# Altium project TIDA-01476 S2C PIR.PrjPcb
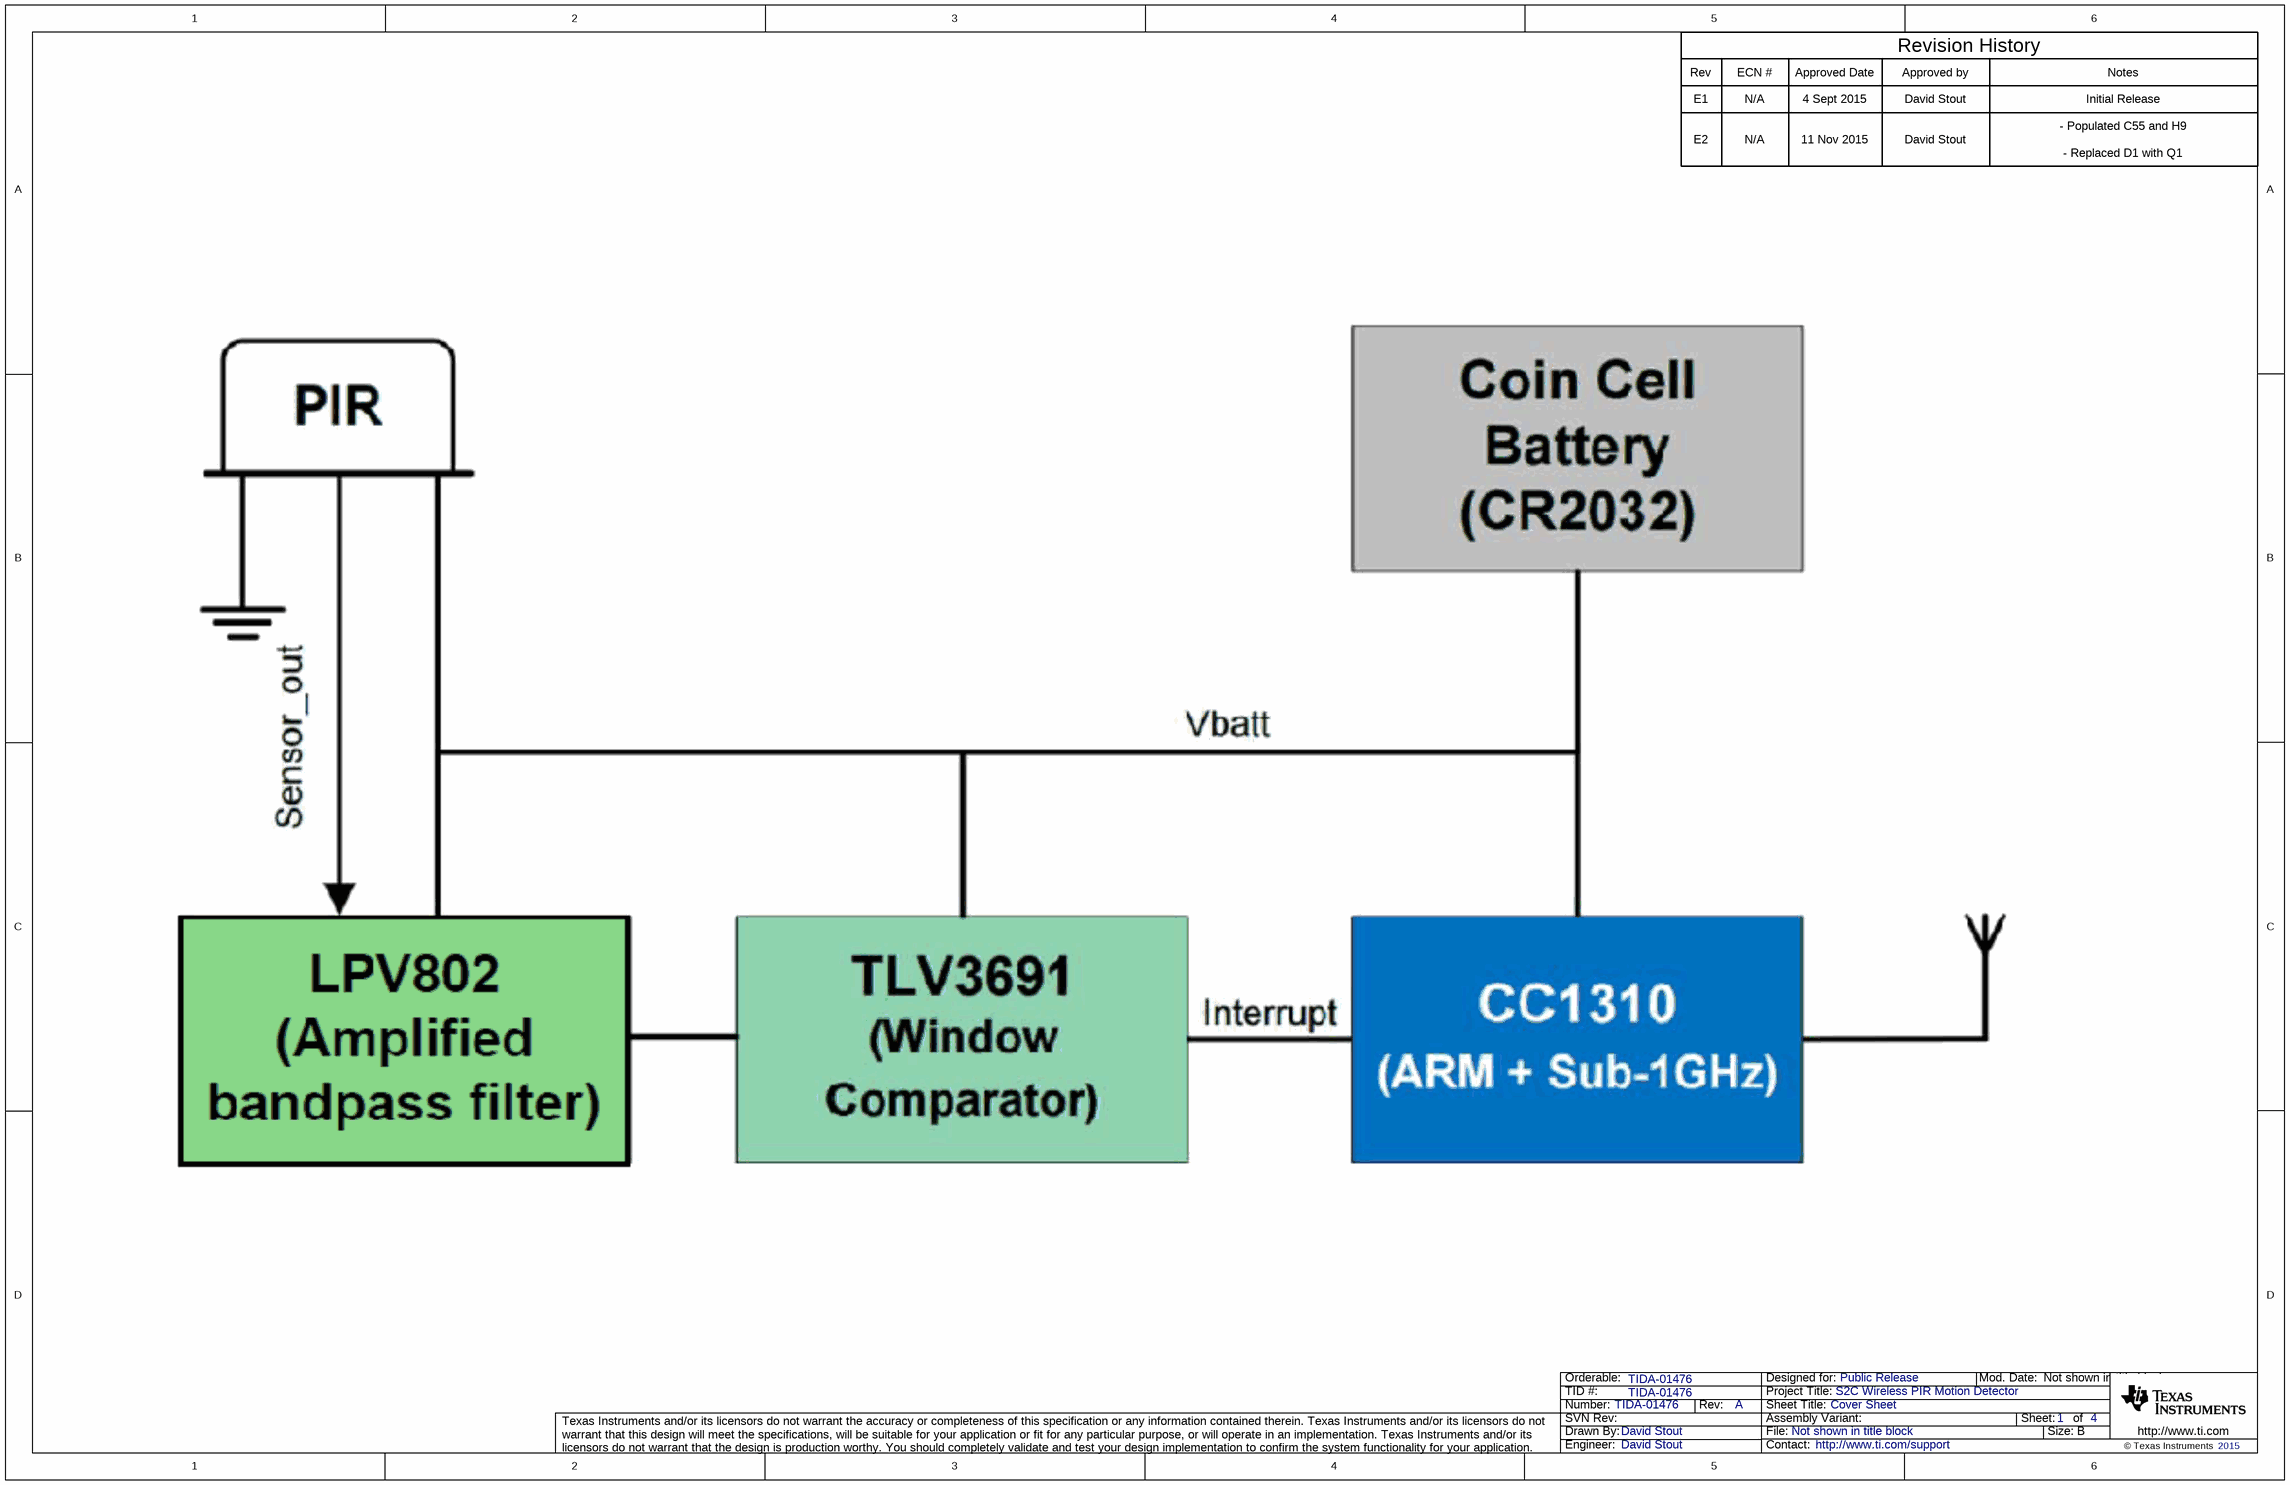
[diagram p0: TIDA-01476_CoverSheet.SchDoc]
CopyrightYear: 2015; EVM_Orderable: TIDA-01476; PCB_Layout: Krypton Solutions/RS; PCB_Rev: A; PRJ_Customer: Public Release; PRJ_Engineer: David Stout; PRJ_Number: TIDA-01476; PRJ_Title: S2C Wireless PIR Motion Detector; SCH_Rev: A; TechSupport: http://www.ti.com/support; TID: TIDA-01476
4 sheets, 141 parts. Net scope: global (net labels, ports and power ports of the same name join across sheets).
Board file: TIDA-01476.PcbDoc
Sheets:
  TIDA-01476_CoverSheet.SchDoc
  TIDA-01476_MCU.SchDoc
  TIDA-01476_POWER_PIR_802.SchDoc
  TIDA-01476_TID_Hardware.SchDoc

## Sheet TIDA-01476_CoverSheet.SchDoc: Cover Sheet
size 431 x 279 mm; Date: Not shown in title block; ApprovedBy: Not shown in title block; CheckedBy: Not shown in title block; Author: Not shown in title block; CompanyName: Not shown in title block; DrawnBy: David Stout; Engineer: Not shown in title block; Organization: Not shown in title block; Address1: Not shown in title block; Address2: Not shown in title block; Address3: Not shown in title block; Address4: Not shown in title block; DocumentNumber: 1; Revision: Use project parameter SCH_Rev; SheetNumber: 1; SheetTotal: 4; PageSetup: Record=PageOptions¦CenterHorizontal=True¦CenterVertical=True¦PrintScale=0.64¦XCorrection=1.00¦YCorrection=1.00¦PrintKind=0¦BorderSize=5000000¦LeftOffset=0¦BottomOffset=0¦Orientation=2¦PaperLength=1000¦PaperWidth=1000¦Scale=100¦PaperSource=15¦PrintQuality=1200¦MediaType=1¦DitherType=10¦PrintScaleMode=1¦PaperKind=Letter¦PaperIndex=1

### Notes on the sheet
- Rev
- E1
- ECN #
- N/A
- Approved Date
- 4 Sept 2015
- Approved by
- David Stout
- Revision History
- Notes
- Initial Release
- E2
- 11 Nov 2015
- - Populated C55 and H9
- - Replaced D1 with Q1

## Sheet TIDA-01476_MCU.SchDoc: Wireless MCU
size 431 x 279 mm; Date: Not shown in title block; ApprovedBy: Not shown in title block; CheckedBy: Not shown in title block; Author: Not shown in title block; CompanyName: Not shown in title block; DrawnBy: Evan Cornell; Engineer: Not shown in title block; Organization: Not shown in title block; Address1: Not shown in title block; Address2: Not shown in title block; Address3: Not shown in title block; Address4: Not shown in title block; DocumentNumber: 1; Revision: Use project parameter SCH_Rev; SheetNumber: 3; SheetTotal: 4; PageSetup: Record=PageOptions¦CenterHorizontal=True¦CenterVertical=True¦PrintScale=1.00¦XCorrection=1.00¦YCorrection=1.00¦PrintKind=0¦BorderSize=5000000¦LeftOffset=0¦BottomOffset=0¦Orientation=2¦PaperLength=1000¦PaperWidth=1000¦Scale=100¦PaperSource=15¦PrintQuality=600¦MediaType=1¦DitherType=10¦PaperKind=Letter¦PrintScaleMode=1
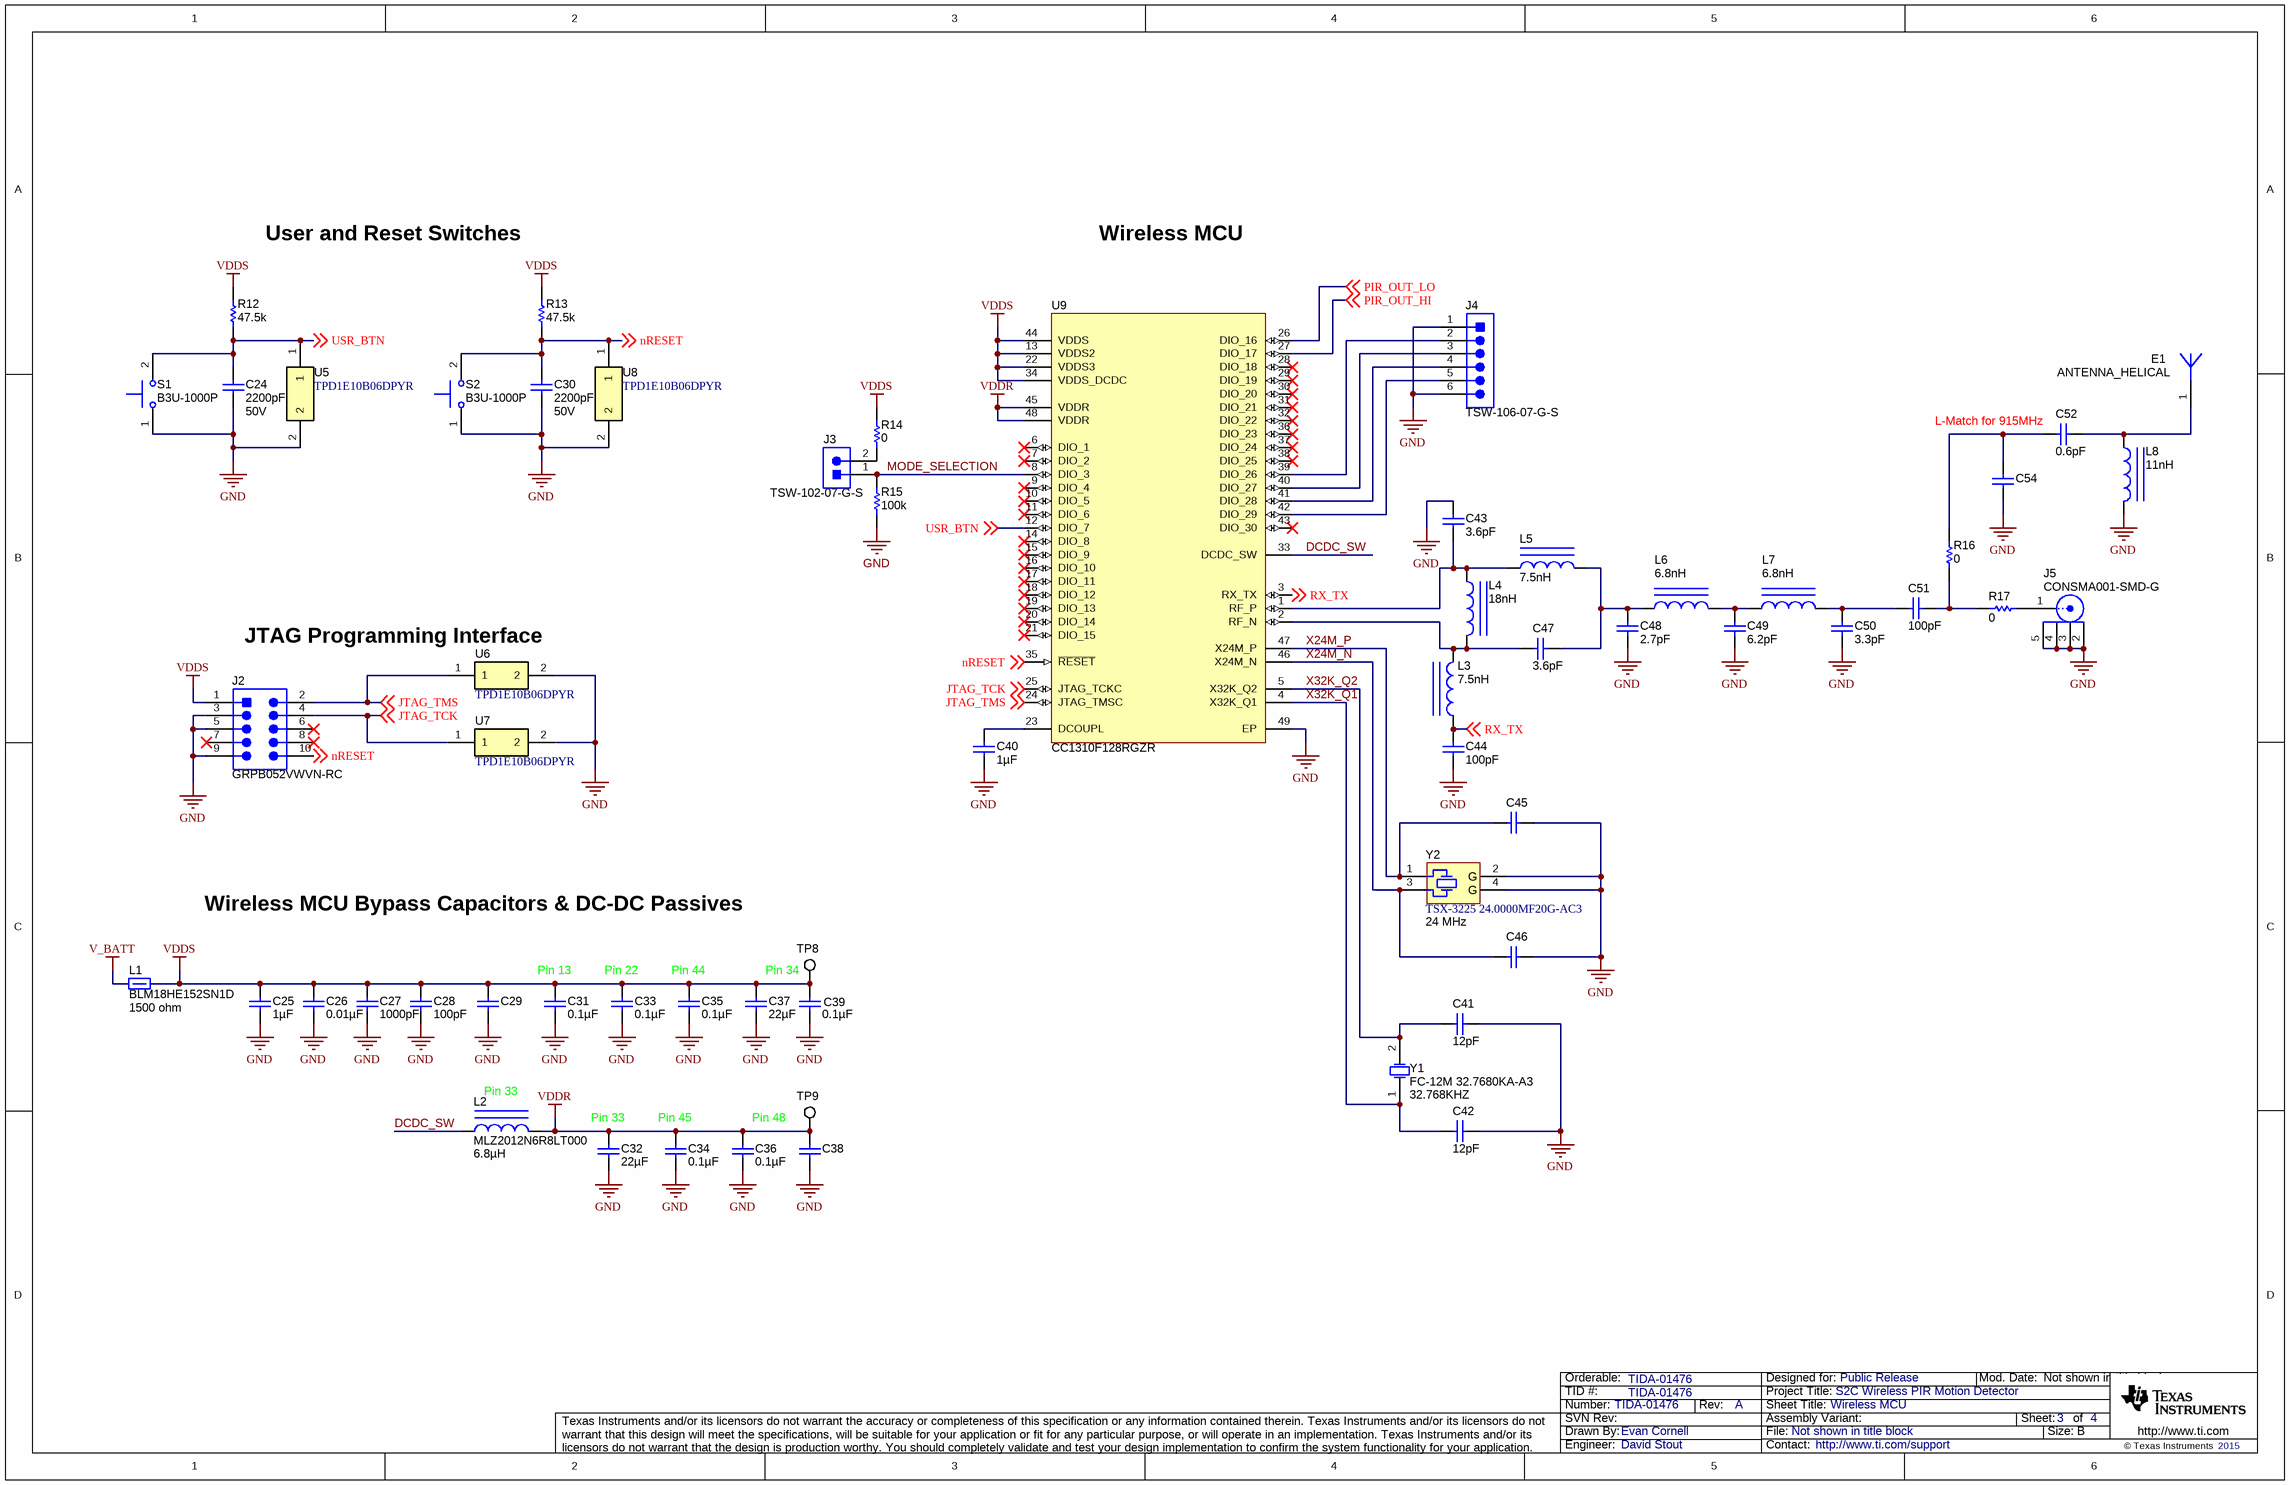
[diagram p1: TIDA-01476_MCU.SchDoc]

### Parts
C24  ValueDisplayed: 2200pF  Value2: 50V  [0402]  (hidden comment: C1005X7R1H222K)
C25  ValueDisplayed: 1µF  [0603]  (hidden comment: C1608X7R1C105K)
C26  ValueDisplayed: 0.01µF  [0402]  (hidden comment: C1005X7R1C103K)
C27  ValueDisplayed: 1000pF  [0402]  (hidden comment: C1005X7R1H102K)
C28  ValueDisplayed: 100pF  [0402]  (hidden comment: C0402C101J3GACTU)
C29  C1608X5R0J226M080AC  [0603L]  (value not drawn)
C30  ValueDisplayed: 2200pF  Value2: 50V  [0402]  (hidden comment: C1005X7R1H222K)
C31  ValueDisplayed: 0.1µF  [0402L]  (hidden comment: GRM155R70J104KA01D)
C32  ValueDisplayed: 22µF  [0603L]  (hidden comment: C1608X5R0J226M080AC)
C33  ValueDisplayed: 0.1µF  [0402L]  (hidden comment: GRM155R70J104KA01D)
C34  ValueDisplayed: 0.1µF  [0402L]  (hidden comment: GRM155R70J104KA01D)
C35  ValueDisplayed: 0.1µF  [0402L]  (hidden comment: GRM155R70J104KA01D)
C36  ValueDisplayed: 0.1µF  [0402L]  (hidden comment: GRM155R70J104KA01D)
C37  ValueDisplayed: 22µF  [0603L]  (hidden comment: C1608X5R0J226M080AC)
C38  GRM155R70J104KA01D  [0402L]  (value not drawn)
C39  ValueDisplayed: 0.1µF  [0402L]  (hidden comment: GRM155R70J104KA01D)
C40  ValueDisplayed: 1µF  [0603L]  (hidden comment: GRM188R70J105KA01D)
C41  ValueDisplayed: 12pF  [0402]  (hidden comment: GRM1555C1E120JA01D)
C42  ValueDisplayed: 12pF  [0402]  (hidden comment: GRM1555C1E120JA01D)
C43  ValueDisplayed: 3.6pF  [0402L]  (hidden comment: GRM1555C1H3R6CA01D)
C44  ValueDisplayed: 100pF  [0402L]  (hidden comment: GRM1555C1H101JA01D)
C45  GRM1555C1E120JA01D  [0402]  (value not drawn)
C46  GRM1555C1E120JA01D  [0402]  (value not drawn)
C47  ValueDisplayed: 3.6pF  [0402L]  (hidden comment: GRM1555C1H3R6CA01D)
C48  ValueDisplayed: 2.7pF  [0402L]  (hidden comment: GRM1555C1H2R7CA01D)
C49  ValueDisplayed: 6.2pF  [0402L]  (hidden comment: GRM1555C1H6R2CA01D)
C50  ValueDisplayed: 3.3pF  [0402L]  (hidden comment: GRM1555C1H3R3CA01D)
C51  ValueDisplayed: 100pF  [0402L]  (hidden comment: GRM1555C1H101JA01D)
C52  value 0.6pF  [0402]  (hidden comment: GJM1555C1HR60BB01D)
C54  GRM1555C1H1R0CA01D  [0402]  (value not drawn)
E1  ANTENNA_HELICAL  [ANTENNA_HELICAL]  (net tie)
J2  GRPB052VWVN-RC  [CONN_GRPB052VWVN-RC]
J3  TSW-102-07-G-S  [TSW-102-07-G-S]
J4  TSW-106-07-G-S  [TSW-106-07-G-S]
J5  CONSMA001-SMD-G  [Linx_CONSMA001-SMD-G]
L1  BLM18HE152SN1D  value 1500 ohm  [0603_095]
L2  MLZ2012N6R8LT000  ValueDisplayed: 6.8µH  [0805_145]
L3  ValueDisplayed: 7.5nH  [LQW15A_00_10]  (hidden comment: LQW15AN7N5G00D)
L4  value 18nH  [LQW15A_00_10]  (hidden comment: LQW15AN18NJ00D)
L5  ValueDisplayed: 7.5nH  [LQW15A_00_10]  (hidden comment: LQW15AN7N5G00D)
L6  value 6.8nH  [LQW15A_00_10]  (hidden comment: LQW15AN6N8G00D)
L7  value 6.8nH  [LQW15A_00_10]  (hidden comment: LQW15AN6N8G00D)
L8  ValueDisplayed: 11nH  [0402]  (hidden comment: LQW15AN11NG00D)
R12  ValueDisplayed: 47.5k  [0402]  (hidden comment: CRCW040247K5FKED)
R13  ValueDisplayed: 47.5k  [0402]  (hidden comment: CRCW040247K5FKED)
R14  ValueDisplayed: 0  [0402]  (hidden comment: CRCW04020000Z0ED)
R15  ValueDisplayed: 100k  [0402]  (hidden comment: CRCW0402100KFKED)
R16  ValueDisplayed: 0  [0402]  (hidden comment: CRCW04020000Z0ED)
R17  ValueDisplayed: 0  [0402]  (hidden comment: CRCW04020000Z0ED)
S1  B3U-1000P  [SW_B3U-1000P]
S2  B3U-1000P  [SW_B3U-1000P]
TP8  5015  [Testpoint_Keystone_Miniature]  (value not drawn)
TP9  5015  [Testpoint_Keystone_Miniature]  (value not drawn)
U5  TPD1E10B06DPYR  [DPY0002A]
U6  TPD1E10B06DPYR  [DPY0002A]
U7  TPD1E10B06DPYR  [DPY0002A]
U8  TPD1E10B06DPYR  [DPY0002A]
U9  CC1310F128RGZR  [RGZ0048A]
Y1  FC-12M 32.7680KA-A3  Frequency: 32.768KHZ  [Epson_FC-12M]
Y2  TSX-3225 24.0000MF20G-AC3  Frequency: 24 MHz  [EPSON_TSX-3225]

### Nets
GND: C24.1 C25.2 C26.2 C27.2 C28.2 C29.2 C30.1 C31.2 C32.2 C33.2 C34.2 C35.2 C36.2 C37.2 C38.2 C39.2 C40.1 C41.1 C42.1 C43.1 C44.2 C45.2 C46.2 C48.2 C49.2 C50.2 C54.2 J2.3 J2.5 J2.9 J4.1 J4.6 J5.2 J5.3 J5.4 J5.5 L8.2 R15.1 S1.1 S2.1 U5.2 U6.2 U7.2 U8.2 U9.49(EP) Y2.2(GND) Y2.4(GND)
V_BATT: L1.2
VDDR: C32.1 C34.1 C36.1 C38.1 L2.2 TP9.1 U9.45(VDDR) U9.48(VDDR)
VDDS: C25.1 C26.1 C27.1 C28.1 C29.1 C31.1 C33.1 C35.1 C37.1 C39.1 J2.1 L1.1 R12.2 R13.2 R14.2 TP8.1 U9.13(VDDS2) U9.22(VDDS3) U9.34(VDDS_DCDC) U9.44(VDDS)
DCDC_SW: L2.1 U9.33(DCDC_SW)
JTAG_TCK: J2.4 U7.1 U9.25(JTAG_TCKC) ; off-sheet JTAG_TCK
JTAG_TMS: J2.2 U6.1 U9.24(JTAG_TMSC) ; off-sheet JTAG_TMS
MODE_SELECTION: J3.1 R15.2 U9.8(DIO_3)
nRESET: C30.2 J2.10 R13.1 S2.2 U8.1 U9.35(~{RESET}) ; off-sheet nRESET
PIR_OUT_HI: U9.27(DIO_17) ; off-sheet PIR_OUT_HI
PIR_OUT_LO: U9.26(DIO_16) ; off-sheet PIR_OUT_LO
RX_TX: C44.1 L3.1 U9.3(RX_TX) ; off-sheet RX_TX
USR_BTN: C24.2 R12.1 S1.2 U5.1 U9.12(DIO_7) ; off-sheet USR_BTN
X24M_N: C46.1 U9.46(X24M_N) Y2.3
X24M_P: C45.1 U9.47(X24M_P) Y2.1
X32K_Q1: C42.2 U9.4(X32K_Q1) Y1.1(OSC1)
X32K_Q2: C41.2 U9.5(X32K_Q2) Y1.2(OSC2)
NetC40_2: C40.2 U9.23(DCOUPL)
NetC43_2: C43.2 L4.1 L5.1 U9.1(RF_P)
NetC47_1: C47.1 C48.1 L5.2 L6.1
NetC47_2: C47.2 L3.2 L4.2 U9.2(RF_N)
NetC49_1: C49.1 L6.2 L7.1
NetC50_1: C50.1 C51.2 L7.2
NetC51_1: C51.1 R16.1 R17.1
NetC52_1: C52.1 C54.1 R16.2
NetC52_2: C52.2 E1.1 L8.1
NetJ3_2: J3.2 R14.1
NetJ4_2: J4.2 U9.39(DIO_26)
NetJ4_3: J4.3 U9.40(DIO_27)
NetJ4_4: J4.4 U9.41(DIO_28)
NetJ4_5: J4.5 U9.42(DIO_29)
NetJ5_1: J5.1 R17.2

Not connected (* = marked no-connect by the designer): J2 6* 7* 8*; U9 6(DIO_1)* 7(DIO_2)* 9(DIO_4)* 10(DIO_5)* 11(DIO_6)* 14(DIO_8)* 15(DIO_9)* 16(DIO_10)* 17(DIO_11)* 18(DIO_12)* 19(DIO_13)* 20(DIO_14)* 21(DIO_15)* 28(DIO_18)* 29(DIO_19)* 30(DIO_20)* 31(DIO_21)* 32(DIO_22)* 36(DIO_23)* 37(DIO_24)* 38(DIO_25)* 43(DIO_30)*

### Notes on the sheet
- User and Reset Switches
- Wireless MCU
- (near C52) L-Match for 915MHz
- (near U6) JTAG Programming Interface
- Wireless MCU Bypass Capacitors & DC-DC Passives
- (near C31) Pin 13
- (near C33) Pin 22
- (near C35) Pin 44
- (near TP8) Pin 34
- (near L2) Pin 33
- (near C32) Pin 33
- (near C34) Pin 45
- Pin 48

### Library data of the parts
C24 C30 = C1005X7R1H222K: CAP, CERM, 2200 pF, 50 V, +/- 10%, X7R, 0402; Manufacturer: TDK; Polarized: N; CompType: Capacitor; Value: 2200pF; U/M: EA; Cap_F: 0.0000000022; Tolerance_%: 10; ESR_ohm: 0.1433; Value1: 0.1433 ohm; VDC_V: 50; TaMin_C: -55; TaMax_C: 125; AEC Category: Q200
C25 = C1608X7R1C105K: CAP, CERM, 1 µF, 16 V, +/- 10%, X7R, 0603; Manufacturer: TDK; Polarized: N; CompType: Capacitor; Value: 1uF; U/M: EA; Cap_F: 0.000001; Tolerance_%: 10; ESR_ohm: 0.0057; Value1: 0.0057 ohm; VDC_V: 16; Value2: 16V; TaMin_C: -55; TaMax_C: 125; AEC Category: Q200
C26 = C1005X7R1C103K: CAP, CERM, 0.01 µF, 16 V, +/- 10%, X7R, 0402; Manufacturer: TDK; Polarized: N; CompType: Capacitor; Value: 0.01uF; U/M: EA; Cap_F: 0.00000001; Tolerance_%: 10; ESR_ohm: 0.0623; Value1: 0.0623 ohm; VDC_V: 16; Value2: 16V; TaMin_C: -55; TaMax_C: 125; AEC Category: Q200
C27 = C1005X7R1H102K: CAP, CERM, 1000 pF, 50 V, +/- 10%, X7R, 0402; Manufacturer: TDK; Polarized: N; CompType: Capacitor; Value: 1000pF; U/M: EA; Cap_F: 0.000000001; Tolerance_%: 10; ESR_ohm: 0.2381; Value1: 0.2381 ohm; VDC_V: 50; Value2: 50V; TaMin_C: -55; TaMax_C: 125; AEC Category: Q200
C28 = C0402C101J3GACTU: CAP, CERM, 100 pF, 25 V, +/- 5%, C0G/NP0, 0402; Manufacturer: Kemet; Polarized: N; CompType: Capacitor; Value: 100pF; U/M: EA; Cap_F: 0.0000000001; Tolerance_%: 5; Value1: Unknown; VDC_V: 25; Value2: 25V; TaMin_C: -55; TaMax_C: 125; AEC Category: Q200
C29 = C1608X5R0J226M080AC: CAP, CERM, 22 µF, 6.3 V, +/- 20%, X5R, 0603; Manufacturer: TDK; Polarized: N; CompType: Capacitor; Value: 22uF; U/M: EA; ValueDisplayed: 22µF; Cap_F: 0.000022; Tolerance_%: 20; Value1: Unknown; VDC_V: 6.3; Value2: 6.3V; TaMin_C: -55; TaMax_C: 85; Cap_Case: 0603; AEC Category: Q200
C31 C33-C36 C39 = GRM155R70J104KA01D: CAP, CERM, 0.1 µF, 6.3 V, +/- 10%, X7R, 0402; Manufacturer: MuRata; Polarized: N; CompType: Capacitor; Value: 0.1uF; U/M: EA; Cap_F: 0.0000001; Tolerance_%: 10; Value1: Unknown; VDC_V: 6.3; Value2: 6.3V; TaMin_C: -55; TaMax_C: 125; Cap_Case: 0402; AEC Category: Q200
C32 C37 = C1608X5R0J226M080AC: CAP, CERM, 22 µF, 6.3 V, +/- 20%, X5R, 0603; Manufacturer: TDK; Polarized: N; CompType: Capacitor; Value: 22uF; U/M: EA; Cap_F: 0.000022; Tolerance_%: 20; Value1: Unknown; VDC_V: 6.3; Value2: 6.3V; TaMin_C: -55; TaMax_C: 85; Cap_Case: 0603; AEC Category: Q200
C38 = GRM155R70J104KA01D: CAP, CERM, 0.1 µF, 6.3 V, +/- 10%, X7R, 0402; Manufacturer: MuRata; Polarized: N; CompType: Capacitor; Value: 0.1uF; U/M: EA; ValueDisplayed: 0.1µF; Cap_F: 0.0000001; Tolerance_%: 10; Value1: Unknown; VDC_V: 6.3; Value2: 6.3V; TaMin_C: -55; TaMax_C: 125; Cap_Case: 0402; AEC Category: Q200
C40 = GRM188R70J105KA01D: CAP, CERM, 1 µF, 6.3 V, +/- 10%, X7R, 0603; Manufacturer: MuRata; Polarized: N; CompType: Capacitor; Value: 1uF; U/M: EA; Cap_F: 0.000001; Tolerance_%: 10; Value1: Unknown; VDC_V: 6.3; Value2: 6.3V; TaMin_C: -55; TaMax_C: 125; Cap_Case: 0603; AEC Category: Q200
C41 C42 C45 C46 = GRM1555C1E120JA01D: CAP, CERM, 12 pF, 25 V, +/- 5%, C0G/NP0, 0402; Manufacturer: MuRata; Polarized: N; CompType: Capacitor; Value: 12pF; U/M: EA; Cap_F: 0.000000000012; Tolerance_%: 5; Value1: Unknown; VDC_V: 25; Value2: 25V; TaMin_C: -55; TaMax_C: 125; AEC Category: Q200
C43 C47 = GRM1555C1H3R6CA01D: CAP, CERM, 3.6 pF, 50 V, +/- 5%, C0G/NP0, 0402; Manufacturer: MuRata; Polarized: N; CompType: Capacitor; Value: 3.6pF; U/M: EA; Cap_F: 0.0000000000036; Tolerance_%: 5; Value1: Unknown; VDC_V: 50; Value2: 50V; TaMin_C: -55; TaMax_C: 125; Cap_Case: 0402; AEC Category: Q200
C44 C51 = GRM1555C1H101JA01D: CAP, CERM, 100 pF, 50 V, +/- 5%, C0G/NP0, 0402; Manufacturer: MuRata; Polarized: N; CompType: Capacitor; Value: 100pF; U/M: EA; Cap_F: 0.0000000001; Tolerance_%: 5; Value1: Unknown; VDC_V: 50; Value2: 50V; TaMin_C: -55; TaMax_C: 125; Cap_Case: 0402; AEC Category: Q200
C48 = GRM1555C1H2R7CA01D: CAP, CERM, 2.7 pF, 50 V, +/- 5%, C0G/NP0, 0402; Manufacturer: MuRata; Polarized: N; CompType: Capacitor; Value: 2.7pF; U/M: EA; Cap_F: 0.0000000000027; Tolerance_%: 5; Value1: Unknown; VDC_V: 50; Value2: 50V; TaMin_C: -55; TaMax_C: 125; Cap_Case: 0402; AEC Category: Q200
C49 = GRM1555C1H6R2CA01D: CAP, CERM, 6.2 pF, 50 V, +/- 5%, C0G/NP0, 0402; Manufacturer: MuRata; Polarized: N; CompType: Capacitor; Value: 6.2pF; U/M: EA; Cap_F: 0.0000000000062; Tolerance_%: 5; Value1: Unknown; VDC_V: 50; Value2: 50V; TaMin_C: -55; TaMax_C: 125; Cap_Case: 0402; AEC Category: Q200
C50 = GRM1555C1H3R3CA01D: CAP, CERM, 3.3 pF, 50 V, +/- 5%, C0G/NP0, 0402; Manufacturer: MuRata; Polarized: N; CompType: Capacitor; Value: 3.3pF; U/M: EA; Cap_F: 0.0000000000033; Tolerance_%: 5; Value1: Unknown; VDC_V: 50; Value2: 50V; TaMin_C: -55; TaMax_C: 125; Cap_Case: 0402; AEC Category: Q200
C52 = Capacitor: CAP, CERM, 0.6pF, 50V, NP0/C0G, +-0.1pF, 0402; Manufacturer: Murata; Polarized: N; U/M: EA
C54 = GRM1555C1H1R0CA01D: CAP, CERM, 1 pF, 50 V, +/- 5%, C0G/NP0, 0402; Manufacturer: MuRata; CompType: Capacitor; Value: 1pF; Value1: Unknown; Value2: 50V; Polarized: N; U/M: EA; Cap_F: 0.000000000001; Tolerance_%: 5; VDC_V: 50; TaMin_C: -55; TaMax_C: 125; AEC Category: Q200
E1 = ANTENNA_HELICAL: PCB Antenna. There is nothing to buy or mount.; SymbolCreator: Altium
J2 = GRPB052VWVN-RC: Header, 50mil, 5x2, Gold, TH; Manufacturer: Sullins Connector Solutions; SymbolCreator: a0412235; U/M: EA
J3 = TSW-102-07-G-S: Header, 100mil, 2x1, Gold, TH; Manufacturer: Samtec; SymbolCreator: a0412235; U/M: EA
J4 = TSW-106-07-G-S: Header, 100mil, 6x1, Gold, TH; Manufacturer: Samtec; SymbolCreator: a0412235; U/M: EA
J5 = CONSMA001-SMD-G: Jack, SMA, PCB, Gold, SMT; Manufacturer: Linx Technologies; SymbolCreator: X0208326; U/M: EA
L1 = BLM18HE152SN1D: Ferrite Bead, 1500 ohm @ 100 MHz, 0.5 A, 0603; Manufacturer: MuRata; Imax_A: 0.5; Value1: 0.5 ohm; Value2: 0.5A; ZTyp@100MHz_Ohm: 1500
L2 = MLZ2012N6R8LT000: Inductor, Multilayer, Ferrite, 6.8 µH, 0.11 A, 0.25 ohm, SMD; Manufacturer: TDK; Value: 6.8uH; Ind_H: 6.8E-6; Imax_A: 0.11; Irms: 0.55A @ 20C rise; Isat: 0.11A @ 50% inductance drop; DCR_ohm: 0.25; Value2: 0.11A; AEC Category: Q200
L3 L5 = LQW15AN7N5G00D: Inductor, Wirewound, 7.5 nH, 0.57 A, 0.13 ohm, SMD; Manufacturer: MuRata; Value: 7.5nH; Ind_H: 7.5E-9; Imax_A: 0.57; Irms: 0.57A @ C rise; DCR_ohm: 0.13; Value2: 0.57A
L4 = LQW15AN18NJ00D: Inductor, Wirewound, 18 nH, 0.37 A, 0.27 ohm, SMD; Manufacturer: MuRata; Ind_H: 18.0E-9; Imax_A: 0.37; DCR_ohm: 0.27; Value2: 0.37A
L6 L7 = LQW15AN6N8G00D: Inductor, Wirewound, 6.8 nH, 0.7 A, 0.09 ohm, SMD; Manufacturer: MuRata; Ind_H: 6.8E-9; Imax_A: 0.7; DCR_ohm: 0.09; Value2: 0.7A
L8 = LQW15AN11NG00D: Inductor, Wirewound, 11 nH, 0.5 A, 0.14 ohm, SMD; Manufacturer: MuRata; Value: 11nH; Ind_H: 11.0E-9; Imax_A: 0.5; Isat: 0.5A @ % inductance drop; DCR_ohm: 0.14; Value2: 0.5A; AEC Category: Q200; AEC Qualified: N
R12 R13 = CRCW040247K5FKED: RES, 47.5 k, 1%, 0.063 W, 0402; Manufacturer: Vishay-Dale; CompType: Resistor; Res_ohm: 47500; Value: 47.5k; Value_Code: 47k5; Tolerance_%: 1; Power_W: 0.063; Value2: 0.063W; VDC_V: 50; TempCo: 100 ppm/C; EIA_Code: E96; U/M: EA; AEC Category: Q200
R14 R16 R17 = CRCW04020000Z0ED: RES, 0, 5%, 0.063 W, 0402; Manufacturer: Vishay-Dale; CompType: Resistor; Value: 0; Value_Code: 0000; Tolerance_%: 5; Power_W: 0.063; Value2: 0.063W; VDC_V: 50; TempCo: 200 ppm/C; EIA_Code: E24; U/M: EA; AEC Category: Q200
R15 = CRCW0402100KFKED: RES, 100 k, 1%, 0.063 W, 0402; Manufacturer: Vishay-Dale; CompType: Resistor; Value: 100k; Res_ohm: 100000; Tolerance_%: 1; Power_W: 0.063; Value2: 0.063W; VDC_V: 50; TempCo: 100 ppm/C; EIA_Code: E96; U/M: EA; AEC Category: Q200
S1 S2 = B3U-1000P: SWITCH TACTILE SPST-NO 0.05A 12V; Manufacturer: Omron Electronic Components; SymbolCreator: a0412235; VDC_V: 12; SwitchFunction: Off-Mom; PositionCount: 1; CurrentRating_mA: 50
TP8 TP9 = 5015: Test Point, Miniature, SMT; Manufacturer: Keystone; CompType: Test Point Loop; U/M: EA
U5-U8 = TPD1E10B06DPYR: ESD in 0402 Package with 10 pF Capacitance and 6 V Breakdown, 1 Channel, -40 to +125 degC, 2-pin X2SON (DPY), Green (RoHS & no Sb/Br); Manufacturer: Texas Instruments; Alternate PartNumber: Equivalent; Breakdown Voltage(Min)(V): 6; Eco-Plan: TBD; IEC 61000-4-2 Air-Gap(+/- kV): 30; IO Capacitance(Typ)(pF): 10; SubFamily: ESD Solution
U9 = CC1310F128RGZR: Sub-1 GHz and 2.4 GHz Multi-standard RF IC Family, RGZ0048A; Alternate PartNumber: CC1310F128RGZT; Manufacturer: Texas Instruments; SymbolCreator: Altium; U/M: EA
Y1 = FC-12M 32.7680KA-A3: Crystal, 32.768kHz, 12.5pF, SMD; Manufacturer: Epson; SymbolCreator: a0412235; U/M: EA; TaMin_C: -40; TaMax_C: 85; Frequency Stability: ±20ppm
Y2 = TSX-3225 24.0000MF20G-AC3: Crystal, 24 MHz, 9 pF, SMD; Manufacturer: Epson; SymbolCreator: a0412235; U/M: EA; TaMin_C: -40; TaMax_C: 85; Frequency Stability: ±20ppm

## Sheet TIDA-01476_POWER_PIR_802.SchDoc: Power and PIR Sensor
size 431 x 279 mm; Date: Not shown in title block; ApprovedBy: Not shown in title block; CheckedBy: Not shown in title block; Author: Not shown in title block; CompanyName: Not shown in title block; DrawnBy: Evan Cornell; Engineer: Not shown in title block; Organization: Not shown in title block; Address1: Not shown in title block; Address2: Not shown in title block; Address3: Not shown in title block; Address4: Not shown in title block; DocumentNumber: 1; Revision: Use project parameter SCH_Rev; SheetNumber: 2; SheetTotal: 4; PageSetup: Record=PageOptions¦CenterHorizontal=True¦CenterVertical=True¦PrintScale=0.64¦XCorrection=1.00¦YCorrection=1.00¦PrintKind=0¦BorderSize=5000000¦LeftOffset=0¦BottomOffset=0¦Orientation=2¦PaperLength=1000¦PaperWidth=1000¦Scale=100¦PaperSource=15¦PrintQuality=600¦MediaType=1¦DitherType=10¦PrintScaleMode=1¦PaperKind=Letter (8.5 x 11")¦PaperIndex=1
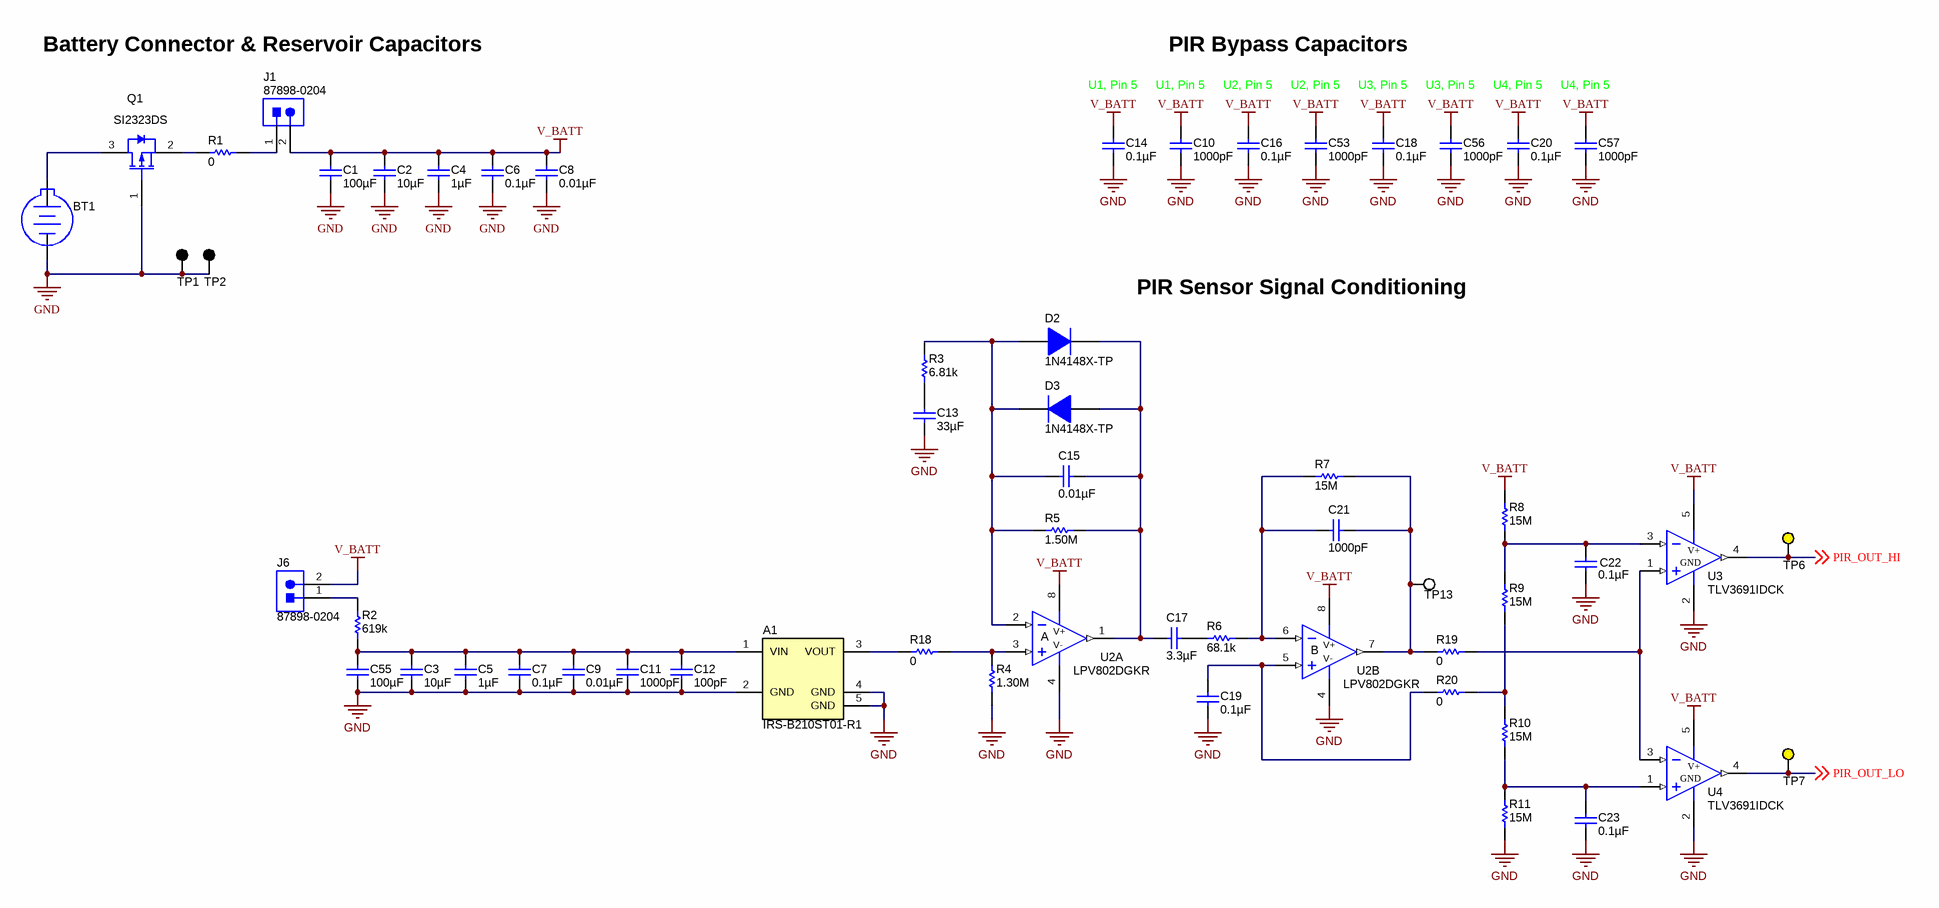
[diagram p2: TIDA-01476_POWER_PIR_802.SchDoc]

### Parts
A1  IRS-B210ST01-R1  [Murata_IRS-B210ST01]
BT1  BS-7  [BAT_BS-7]  (value not drawn)
C1  ValueDisplayed: 100µF  [1206_190]  (hidden comment: C3216X5R1A107M160AC)
C2  ValueDisplayed: 10µF  [0603]  (hidden comment: C1608X5R0J106M)
C3  ValueDisplayed: 10µF  [0402]  (hidden comment: GRM155R60J106ME44D)
C4  ValueDisplayed: 1µF  [0603]  (hidden comment: C1608X7R1C105K)
C5  ValueDisplayed: 1µF  [0402]  (hidden comment: C1005X5R1A105K050BB)
C6  ValueDisplayed: 0.1µF  [0402]  (hidden comment: C1005X7R1H104K050BB)
C7  ValueDisplayed: 0.1µF  [0402]  (hidden comment: C1005X7R1H104K050BB)
C8  ValueDisplayed: 0.01µF  [0402]  (hidden comment: C1005X7R1C103K)
C9  ValueDisplayed: 0.01µF  [0402]  (hidden comment: C1005X7R1C103K)
C10  ValueDisplayed: 1000pF  [0402]  (hidden comment: C1005X7R1H102K)
C11  ValueDisplayed: 1000pF  [0402]  (hidden comment: C1005X7R1H102K)
C12  ValueDisplayed: 100pF  [0402]  (hidden comment: C0402C101J3GACTU)
C13  ValueDisplayed: 33µF  [0805_145]  (hidden comment: C2012X5R1A336M125AC)
C14  ValueDisplayed: 0.1µF  [0402]  (hidden comment: C1005X7R1H104K)
C15  ValueDisplayed: 0.01µF  [0402]  (hidden comment: C1005X7R1E103K)
C16  ValueDisplayed: 0.1µF  [0402]  (hidden comment: C1005X7R1H104K)
C17  ValueDisplayed: 3.3µF  [0402]  (hidden comment: C1005X5R1A335K050BC)
C18  ValueDisplayed: 0.1µF  [0402]  (hidden comment: C1005X7R1H104K)
C19  ValueDisplayed: 0.1µF  [0402]  (hidden comment: C1005X7R1H104K)
C20  ValueDisplayed: 0.1µF  [0402]  (hidden comment: C1005X7R1H104K)
C21  ValueDisplayed: 1000pF  [0402]  (hidden comment: C1005C0G1E102J)
C22  ValueDisplayed: 0.1µF  [0402]  (hidden comment: C1005X7R1H104K)
C23  ValueDisplayed: 0.1µF  [0402]  (hidden comment: C1005X7R1H104K)
C53  ValueDisplayed: 1000pF  [0402]  (hidden comment: C1005X7R1H102K)
C55  ValueDisplayed: 100µF  [1206_190]  (hidden comment: C3216X5R1A107M160AC)
C56  ValueDisplayed: 1000pF  [0402]  (hidden comment: C1005X7R1H102K)
C57  ValueDisplayed: 1000pF  [0402]  (hidden comment: C1005X7R1H102K)
D2  1N4148X-TP  [SOD-523]
D3  1N4148X-TP  [SOD-523]
J1  87898-0204  [Molex_87898-0204]
J6  87898-0204  [Molex_87898-0204]
Q1  SI2323DS  [SOT-23]
R1  ValueDisplayed: 0  [0805_HV]  (hidden comment: CRCW08050000Z0EA)
R2  ValueDisplayed: 619k  [0402]  (hidden comment: CRCW0402619KFKED)
R3  ValueDisplayed: 6.81k  [0402]  (hidden comment: CRCW04026K81FKED)
R4  ValueDisplayed: 1.30M  [0402]  (hidden comment: CRCW04021M30FKED)
R5  ValueDisplayed: 1.50M  [0402]  (hidden comment: CRCW04021M50FKED)
R6  ValueDisplayed: 68.1k  [0402]  (hidden comment: CRCW040268K1FKED)
R7  ValueDisplayed: 15M  [0805_HV]  (hidden comment: RMCF0805JT15M0)
R8  ValueDisplayed: 15M  [0805_HV]  (hidden comment: RMCF0805JT15M0)
R9  ValueDisplayed: 15M  [0805_HV]  (hidden comment: RMCF0805JT15M0)
R10  ValueDisplayed: 15M  [0805_HV]  (hidden comment: RMCF0805JT15M0)
R11  ValueDisplayed: 15M  [0805_HV]  (hidden comment: RMCF0805JT15M0)
R18  ValueDisplayed: 0  [0402]  (hidden comment: CRCW04020000Z0ED)
R19  ValueDisplayed: 0  [0402]  (hidden comment: CRCW04020000Z0ED)
R20  ValueDisplayed: 0  [0402]  (hidden comment: CRCW04020000Z0ED)
TP1  5001  [Keystone5001]  (value not drawn)
TP2  5001  [Keystone5001]  (value not drawn)
TP6  5004  [Keystone5004]  (value not drawn)
TP7  5004  [Keystone5004]  (value not drawn)
TP13  5015  [Testpoint_Keystone_Miniature]  (value not drawn)
U2  LPV802DGKR  [DGK0008A_N]  (parts A,B of 2)
U3  TLV3691IDCK  [DCK0005A_N]
U4  TLV3691IDCK  [DCK0005A_N]

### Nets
GND: A1.2(GND) A1.4(GND) A1.5(GND) BT1.2(-) C1.2 C2.2 C3.2 C4.2 C5.2 C6.2 C7.2 C8.2 C9.2 C10.2 C11.2 C12.2 C13.2 C14.1 C16.1 C18.1 C19.2 C20.1 C22.2 C23.2 C53.2 C55.2 C56.2 C57.2 Q1.1(G) R4.1 R11.1 TP1.1 TP2.1 U2.4(V-) U3.2(GND) U4.2(GND)
V_BATT: C1.1 C2.1 C4.1 C6.1 C8.1 C10.1 C14.2 C16.2 C18.2 C20.2 C53.1 C56.1 C57.1 J1.2 J6.2 R8.2 U2.8(V+) U3.5(V+) U4.5(V+)
PIR_OUT_HI: TP6.1 U3.4(OUT) ; off-sheet PIR_OUT_HI
PIR_OUT_LO: TP7.1 U4.4(OUT) ; off-sheet PIR_OUT_LO
NetA1_1: A1.1(VIN) C3.1 C5.1 C7.1 C9.1 C11.1 C12.1 C55.1 R2.1
NetA1_3: A1.3(VOUT) R18.1
NetBT1_1: BT1.1(+) Q1.3(D)
NetC13_1: C13.1 R3.1
NetC15_1: C15.1 C17.2 D2.1(K) D3.2(A) R5.2 U2.1(OUT)
NetC15_2: C15.2 D2.2(A) D3.1(K) R3.2 R5.1 U2.2(IN-)
NetC17_1: C17.1 R6.1
NetC19_1: C19.1 R20.1 U2.5(IN+)
NetC21_1: C21.1 R7.2 R19.1 TP13.1 U2.7(OUT)
NetC21_2: C21.2 R6.2 R7.1 U2.6(IN-)
NetC22_1: C22.1 R8.1 R9.2 U3.3(IN-)
NetC23_1: C23.1 R10.1 R11.2 U4.1(IN+)
NetJ1_1: J1.1 R1.2
NetJ6_1: J6.1 R2.2
NetQ1_2: Q1.2(S) R1.1
NetR4_2: R4.2 R18.2 U2.3(IN+)
NetR9_1: R9.1 R10.2 R20.2
NetR19_2: R19.2 U3.1(IN+) U4.3(IN-)

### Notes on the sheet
- Battery Connector & Reservoir Capacitors
- PIR Bypass Capacitors
- U1, Pin 5
- U2, Pin 5
- U3, Pin 5
- U4, Pin 5
- PIR Sensor Signal Conditioning

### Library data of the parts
A1 = IRS-B210ST01-R1: Pyroelectric Infrared Sensors for Reflow Soldering, 3.6mVp-p, SMD; Manufacturer: MuRata; SymbolCreator: Altium; CompType: SENSOR
BT1 = BS-7: Battery Holder, CR2032, Retainer clip, TH; Manufacturer: Memory Protection Devices; SymbolCreator: a0412235
C1 C55 = C3216X5R1A107M160AC: CAP, CERM, 100 µF, 10 V, +/- 20%, X5R, 1206_190; Manufacturer: TDK; Polarized: N; CompType: Capacitor; Value: 100uF; U/M: EA; Cap_F: 0.0001; Tolerance_%: 20; Value1: Unknown; VDC_V: 10; Value2: 10V; TaMin_C: -55; TaMax_C: 85; Cap_Case: 1206; AEC Category: Q200
C2 = C1608X5R0J106M: CAP, CERM, 10 µF, 6.3 V, +/- 20%, X5R, 0603; Manufacturer: TDK; Polarized: N; CompType: Capacitor; Value: 10uF; U/M: EA; Cap_F: 0.00001; Tolerance_%: 20; ESR_ohm: 0.005; Value1: 0.005 ohm; VDC_V: 6.3; Value2: 6.3V; IRMS_A: 1.9; TaMin_C: -25; TaMax_C: 85; AEC Category: Q200
C3 = GRM155R60J106ME44D: CAP, CERM, 10 µF, 6.3 V, +/- 20%, X5R, 0402; Manufacturer: MuRata; Polarized: N; CompType: Capacitor; Value: 10uF; U/M: EA; Cap_F: 0.00001; Tolerance_%: 20; Value1: Unknown; VDC_V: 6.3; Value2: 6.3V; TaMin_C: -55; TaMax_C: 85; AEC Category: Q200
C4 = C1608X7R1C105K: as C25 on sheet TIDA-01476_MCU
C5 = C1005X5R1A105K050BB: CAP, CERM, 1 µF, 10 V, +/- 10%, X5R, 0402; Manufacturer: TDK; Polarized: N; CompType: Capacitor; Value: 1uF; U/M: EA; Cap_F: 0.000001; Tolerance_%: 10; Value1: Unknown; Value2: 10V; TaMin_C: -55; TaMax_C: 85; AEC Category: Q200
C6 C7 = C1005X7R1H104K050BB: CAP, CERM, 0.1 µF, 50 V, +/- 10%, X7R, 0402; Manufacturer: TDK; Polarized: N; CompType: Capacitor; Value: 0.1uF; U/M: EA; Cap_F: 0.0000001; Tolerance_%: 10; Value1: Unknown; VDC_V: 50; Value2: 50V; TaMin_C: -55; TaMax_C: 125; AEC Category: Q200
C8 C9 = C1005X7R1C103K: as C26 on sheet TIDA-01476_MCU
C10 C11 C53 C56 C57 = C1005X7R1H102K: as C27 on sheet TIDA-01476_MCU
C12 = C0402C101J3GACTU: as C28 on sheet TIDA-01476_MCU
C13 = C2012X5R1A336M125AC: CAP, CERM, 33 µF, 10 V, +/- 20%, X5R, 0805; Manufacturer: TDK; Polarized: N; CompType: Capacitor; Value: 33uF; U/M: EA; Cap_F: 0.000033; Tolerance_%: 20; Value1: Unknown; VDC_V: 10; Value2: 10V; TaMin_C: -55; TaMax_C: 85; Cap_Case: 0805; AEC Category: Q200
C14 C16 C18-C20 C22 C23 = C1005X7R1H104K: CAP, CERM, 0.1 µF, 50 V, +/- 10%, X7R, 0402; Manufacturer: TDK; Polarized: N; CompType: Capacitor; Value: 0.1uF; U/M: EA; Cap_F: 0.0000001; Tolerance_%: 10; Value1: Unknown; VDC_V: 50; Value2: 50V; TaMin_C: -55; TaMax_C: 125; AEC Category: Q200
C15 = C1005X7R1E103K: CAP, CERM, 0.01 µF, 25 V, +/- 10%, X7R, 0402; Manufacturer: TDK; Polarized: N; CompType: Capacitor; Value: 0.01uF; U/M: EA; Cap_F: 0.00000001; Tolerance_%: 10; ESR_ohm: 0.0623; Value1: 0.0623 ohm; VDC_V: 25; Value2: 25V; TaMin_C: -55; TaMax_C: 125; AEC Category: Q200
C17 = C1005X5R1A335K050BC: CAP, CERM, 3.3 µF, 10 V, +/- 10%, X5R, 0402; Manufacturer: TDK; Polarized: N; CompType: Capacitor; Value: 3.3uF; U/M: EA; Cap_F: 0.0000033; Tolerance_%: 10; Value1: Unknown; Value2: 10V; TaMin_C: -55; TaMax_C: 85; AEC Category: Q200
C21 = C1005C0G1E102J: CAP, CERM, 1000 pF, 25 V, +/- 5%, C0G/NP0, 0402; Manufacturer: TDK; Polarized: N; CompType: Capacitor; Value: 1000pF; U/M: EA; Cap_F: 0.000000001; Tolerance_%: 5; Value1: Unknown; VDC_V: 25; Value2: 25V; TaMin_C: -55; TaMax_C: 125; AEC Category: Q200
D2 D3 = 1N4148X-TP: Diode, Switching, 75 V, 0.3 A, SOD-523; Manufacturer: Micro Commercial Components; U/M: EA; Vf_V: 1.25; Value: 75V; Value1: 0.3A; Value2: 1.25V; Io_A: 0.3; Vr_V: 75; TJmax_C: 150; AEC Category: Q101
J1 J6 = 87898-0204: Header, 2.54 mm, 2x1, Gold, R/A, SMT; Manufacturer: Molex; SymbolCreator: a0412235; U/M: EA
Q1 = SI2323DS: MOSFET, P-CH, -20 V, -3.7 A, SOT-23; Manufacturer: Vishay-Siliconix; Alternate Manufacturer: None; U/M: EA; ChType: P; Value: -20V; Value1: 0.031 ohm; Rdson45_ohm: 0.031; Value2: 12.5 nC; QgTyp_nC: 12.5; Vgs_V: -8; AEC Category: Q101
R1 = CRCW08050000Z0EA: RES, 0, 5%, 0.125 W, 0805; Manufacturer: Vishay-Dale; CompType: Resistor; Value: 0; Value_Code: 0000; Tolerance_%: 5; Power_W: 0.125; Value2: 0.125W; VDC_V: 150; TempCo: 200 ppm/C; EIA_Code: E24; U/M: EA; AEC Category: Q200
R2 = CRCW0402619KFKED: RES, 619 k, 1%, 0.063 W, 0402; Manufacturer: Vishay-Dale; CompType: Resistor; Value: 619k; Res_ohm: 619000; Tolerance_%: 1; Power_W: 0.063; Value2: 0.063W; VDC_V: 50; TempCo: 100 ppm/C; EIA_Code: E96; U/M: EA; AEC Category: Q200
R3 = CRCW04026K81FKED: RES, 6.81 k, 1%, 0.063 W, 0402; Manufacturer: Vishay-Dale; CompType: Resistor; Value: 6.81k; Res_ohm: 6810; Value_Code: 6k81; Tolerance_%: 1; Power_W: 0.063; Value2: 0.063W; VDC_V: 50; TempCo: 100 ppm/C; EIA_Code: E96; U/M: EA; AEC Category: Q200
R4 = CRCW04021M30FKED: RES, 1.30 M, 1%, 0.063 W, 0402; Manufacturer: Vishay-Dale; CompType: Resistor; Value: 1.30Meg; Res_ohm: 1300000; Value_Code: 1M30; Tolerance_%: 1; Power_W: 0.063; Value2: 0.063W; VDC_V: 50; TempCo: 100 ppm/C; EIA_Code: E96; U/M: EA; AEC Category: Q200
R5 = CRCW04021M50FKED: RES, 1.50 M, 1%, 0.063 W, 0402; Manufacturer: Vishay-Dale; CompType: Resistor; Value: 1.50Meg; Res_ohm: 1500000; Value_Code: 1M50; Tolerance_%: 1; Power_W: 0.063; Value2: 0.063W; VDC_V: 50; TempCo: 100 ppm/C; EIA_Code: E96; U/M: EA; AEC Category: Q200
R6 = CRCW040268K1FKED: RES, 68.1 k, 1%, 0.063 W, 0402; Manufacturer: Vishay-Dale; CompType: Resistor; Value: 68.1k; Res_ohm: 68100; Value_Code: 68k1; Tolerance_%: 1; Power_W: 0.063; Value2: 0.063W; VDC_V: 50; TempCo: 100 ppm/C; EIA_Code: E96; U/M: EA; AEC Category: Q200
R7-R11 = RMCF0805JT15M0: RES, 15 M, 5%, 0.125 W, AEC-Q200 Grade 0, 0805; Manufacturer: Stackpole Electronics Inc; CompType: Resistor; Value: 15Meg; Res_ohm: 15000000; Value_Code: 15M0; Tolerance_%: 5; Power_W: 0.125; Value2: 0.125W; VDC_V: 75; TempCo: 200 ppm/C; U/M: EA; AEC Category: Q200; AEC Qualified: Y; AEC Grade: 0
R18-R20 = CRCW04020000Z0ED: as R14 on sheet TIDA-01476_MCU
TP1 TP2 = 5001: Test Point, Miniature, Black, TH; Manufacturer: Keystone; CompType: Test Point Loop; U/M: EA
TP6 TP7 = 5004: Test Point, Miniature, Yellow, TH; Manufacturer: Keystone; CompType: Test Point Loop; U/M: EA
TP13 = 5015: as TP8 on sheet TIDA-01476_MCU
U2 = LPV802DGKR: 350 nA Rail-to-Rail I/O Nanopower Operational Amplifier Family, DGK0008A; Alternate PartNumber: LPV802DGKT; Manufacturer: Texas Instruments; CompType: IC; SizeArea_mm2: 15.655; SizeAreaWB_mm2: 35.955; SizeX_mm: 5.05; SizeY_mm: 3.1; SizeZ_mm: 1.1; U/M: EA
U3 U4 = TLV3691IDCK: 0.9-V to 6.5-V, Nanopower Comparator, DCK0005A; Manufacturer: Texas Instruments; SymbolCreator: OpAmp IC; CompType: IC; U/M: EA

## Sheet TIDA-01476_TID_Hardware.SchDoc: Hardware
size 431 x 279 mm; Date: Not shown in title block; ApprovedBy: Not shown in title block; CheckedBy: Not shown in title block; Author: Not shown in title block; CompanyName: Not shown in title block; DrawnBy: Evan Cornell; Engineer: Not shown in title block; Organization: Not shown in title block; Address1: Not shown in title block; Address2: Not shown in title block; Address3: Not shown in title block; Address4: Not shown in title block; DocumentNumber: 1; Revision: Use project parameter SCH_Rev; SheetNumber: 4; SheetTotal: 4; PageSetup: Record=PageOptions¦CenterHorizontal=True¦CenterVertical=True¦PrintScale=1.00¦XCorrection=1.00¦YCorrection=1.00¦PrintKind=0¦BorderSize=5000000¦LeftOffset=0¦BottomOffset=0¦Orientation=2¦PaperLength=1000¦PaperWidth=1000¦Scale=100¦PaperSource=15¦PrintQuality=600¦MediaType=1¦DitherType=10¦PaperKind=Letter¦PrintScaleMode=1
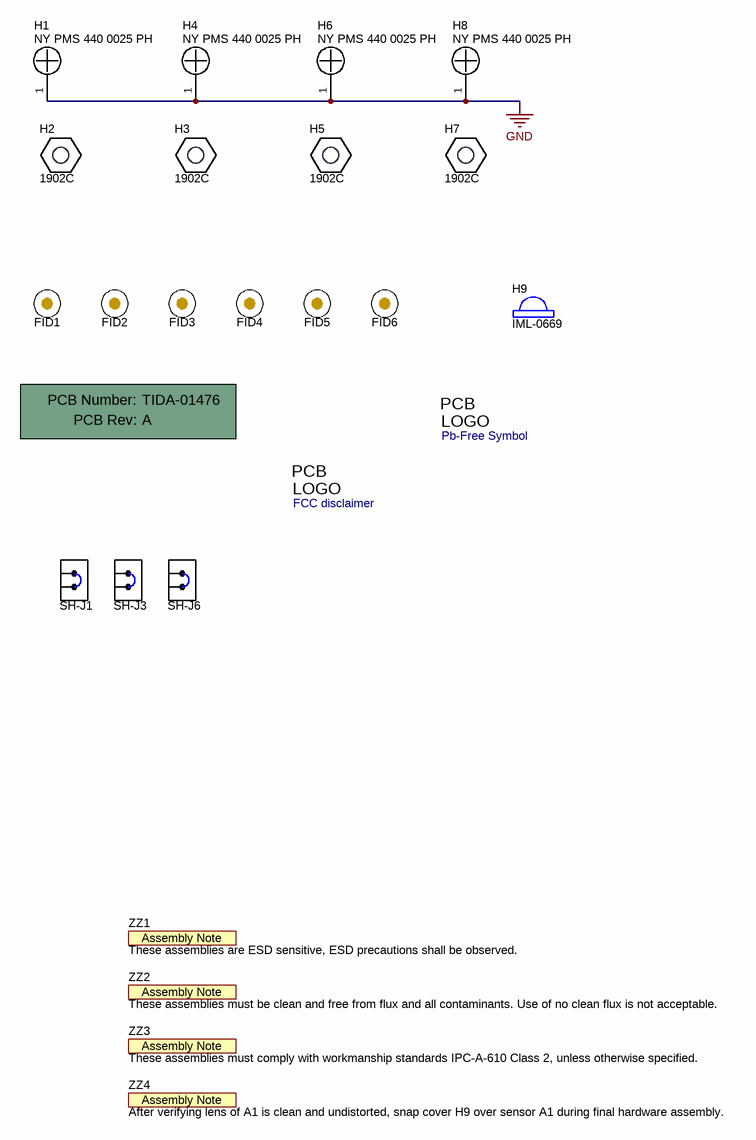
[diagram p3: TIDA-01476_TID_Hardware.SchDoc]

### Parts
!PCB1  Printed Circuit Board  (value not drawn)  (mechanical)
FID1  Fiducial  [Fiducial10-20]  (value not drawn)
FID2  Fiducial  [Fiducial10-20]  (value not drawn)
FID3  Fiducial  [Fiducial10-20]  (value not drawn)
FID4  Fiducial  [Fiducial10-20]  (value not drawn)
FID5  Fiducial  [Fiducial10-20]  (value not drawn)
FID6  Fiducial  [Fiducial10-20]  (value not drawn)
H1  NY PMS 440 0025 PH  [NY PMS 440 0025 PH]
H2  1902C  [Keystone_1902C]
H3  1902C  [Keystone_1902C]
H4  NY PMS 440 0025 PH  [NY PMS 440 0025 PH]
H5  1902C  [Keystone_1902C]
H6  NY PMS 440 0025 PH  [NY PMS 440 0025 PH]
H7  1902C  [Keystone_1902C]
H8  NY PMS 440 0025 PH  [NY PMS 440 0025 PH]
H9  IML-0669  [Murata_IML-0669]
Logo1  FCC disclaimer  [FCC_disclaimer_stacked]  (no BOM)
Logo3  Pb-Free Symbol  [Pb-Free_Overlay_Small]  (no BOM)
SH-J1  969102-0000-DA  [SNT-100-BK-G]  (value not drawn)
SH-J3  969102-0000-DA  [SNT-100-BK-G]  (value not drawn)
SH-J6  969102-0000-DA  [SNT-100-BK-G]  (value not drawn)
ZZ1  These assemblies are ESD sensitive, ESD precautions shall be observed.  [AssemblyNote]  (no BOM)
ZZ2  These assemblies must be clean and free from flux and all contaminants. Use of no clean flux is not acceptable.  [AssemblyNote]  (no BOM)
ZZ3  These assemblies must comply with workmanship standards IPC-A-610 Class 2, unless otherwise specified.  [AssemblyNote]  (no BOM)
ZZ4  After verifying lens of A1 is clean and undistorted, snap cover H9 over sensor A1 during final hardware assembly.  [AssemblyNote]  (no BOM)

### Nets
GND: H1.1 H4.1 H6.1 H8.1

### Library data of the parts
!PCB1 = PCB: Manufacturer: Any; PartNumber: TIDA-01476; SymbolCreator: a0412235
FID1-FID6 = Fiducial: Fiducial mark.  There is nothing to buy or mount.; SymbolCreator: codlsc
H1 H4 H6 H8 = NY PMS 440 0025 PH: Machine Screw, Round, #4-40 x 1/4, Nylon, Philips panhead; Manufacturer: B&F Fastener Supply; CompType: Hardware; SymbolCreator: codlsc; U/M: EA
H2 H3 H5 H7 = 1902C: Standoff, Hex, 0.5"L #4-40 Nylon; Manufacturer: Keystone; CompType: Hardware; SymbolCreator: a0412235
H9 = IML-0669: Lens, Ceiling Mount, TH; Manufacturer: MuRata; SymbolCreator: Altium
Logo1 = FCC_disclaimer: SymbolCreator: codlsc
Logo3 = Pb-Free: SymbolCreator: a0412235
SH-J1 SH-J3 SH-J6 = 969102-0000-DA: Shunt, 100mil, Gold plated, Black; Manufacturer: 3M; Alternate Manufacturer: Samtec; Value: 1x2; Note: You can "mate" this to a header by matching the designator.  i.e. use SH-J3 for header J3
ZZ1-ZZ4 = AssemblyNote: SymbolCreator: codlsc

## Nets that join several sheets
GND: TIDA-01476_MCU (47 pins), TIDA-01476_POWER_PIR_802 (36 pins), TIDA-01476_TID_Hardware (H1.1 H4.1 H6.1 H8.1)
V_BATT: TIDA-01476_MCU (L1.2), TIDA-01476_POWER_PIR_802 (19 pins)
PIR_OUT_HI: TIDA-01476_MCU (U9.27), TIDA-01476_POWER_PIR_802 (TP6.1 U3.4)
PIR_OUT_LO: TIDA-01476_MCU (U9.26), TIDA-01476_POWER_PIR_802 (TP7.1 U4.4)

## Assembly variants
001: not fitted C29 C38 C45 C46 C54 FID1 FID2 FID3 FID4 FID5 FID6 J4 J5 R17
